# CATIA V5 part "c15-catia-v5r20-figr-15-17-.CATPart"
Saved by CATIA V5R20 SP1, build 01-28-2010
Part number: Part1
Bounding box of the stored display mesh (mm): x -46.56 to 46.56, y -26.965 to 25.965, z 0 to 40
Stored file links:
  D:\v5_r20\psrt_files_downloaded\c15\c15-catia-v5r20-figr-15-17-.CATPart
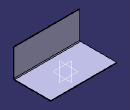
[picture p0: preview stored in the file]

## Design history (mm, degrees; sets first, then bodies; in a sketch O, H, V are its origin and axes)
SheetMetalParameters1: Thickness 1, BendRadius 1, KFactor 0.325257 {= log(min(100,max(20*SheetMetalParameters1.BendRadius,SheetMetalParameters1.Thickness)/SheetMetalParameters1.Thickness))/log(100)/2}, ReliefRadialLength 1, ReliefAxialLength 2, MinimumBendRadius 0
Body1 (main body)
  Sketch1 on xy-plane, origin (0, 0, 0), H (1, 0, 0), V (0, 1, 0)
    line L1 (-46.5596, 25.9646) -> (46.5596, 25.9646)
    line L2 (46.5596, 25.9646) -> (46.5596, -25.9646)
    line L3 (46.5596, -25.9646) -> (-46.5596, -25.9646)
    line L4 (-46.5596, -25.9646) -> (-46.5596, 25.9646)
    horizontal: L1 H, L3 H
    vertical: L2 V, L4 V
    symmetry: L1 L3 H, L4 L2 V
  Wall1: Thickness 1, Profile Sketch1
  d_NewWallOnEdge1: NewWallOnEdge_Edge edge [face of Wall1 | face of Wall1], NewWallOnEdge_Length 40, NewWallOnEdge_HeightLimitOffset 0, NewWallOnEdge_WidthOffset1 0, NewWallOnEdge_WidthOffset2 0, NewWallOnEdge_Angle 90, NewWallOnEdge_BendRadiusValue 1 {= SheetMetalParameters1.BendRadius}, NewWallOnEdge_BendTable SheetMetalParameters1, KFacteur 0.325257 {= log(min(100,max(20*d_NewWallOnEdge1.Radius,SheetMetalParameters1.Thickness)/SheetMetalParameters1.Thickness))/log(100)/2}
